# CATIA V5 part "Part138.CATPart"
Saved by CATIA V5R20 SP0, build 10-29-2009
Part number: DFA 084700-1
Revision: ANY
Definition: UNKNOWN
Nomenclature: DFA 084700-1
Source: Unknown
Bounding box of the stored display mesh (mm): x -2.853 to 2.853, y 0.2 to 2.5, z -3 to 3
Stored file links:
  C:\Users\Utente\Desktop\IO LAVORO\3D X SITO CF\CUMSA\3D files FA\FA 084712-21\Part138.CATPart

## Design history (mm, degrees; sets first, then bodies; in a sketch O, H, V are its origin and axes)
Body1 "Cortar-Extruir1" (main body)
  Solid1: solid without history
